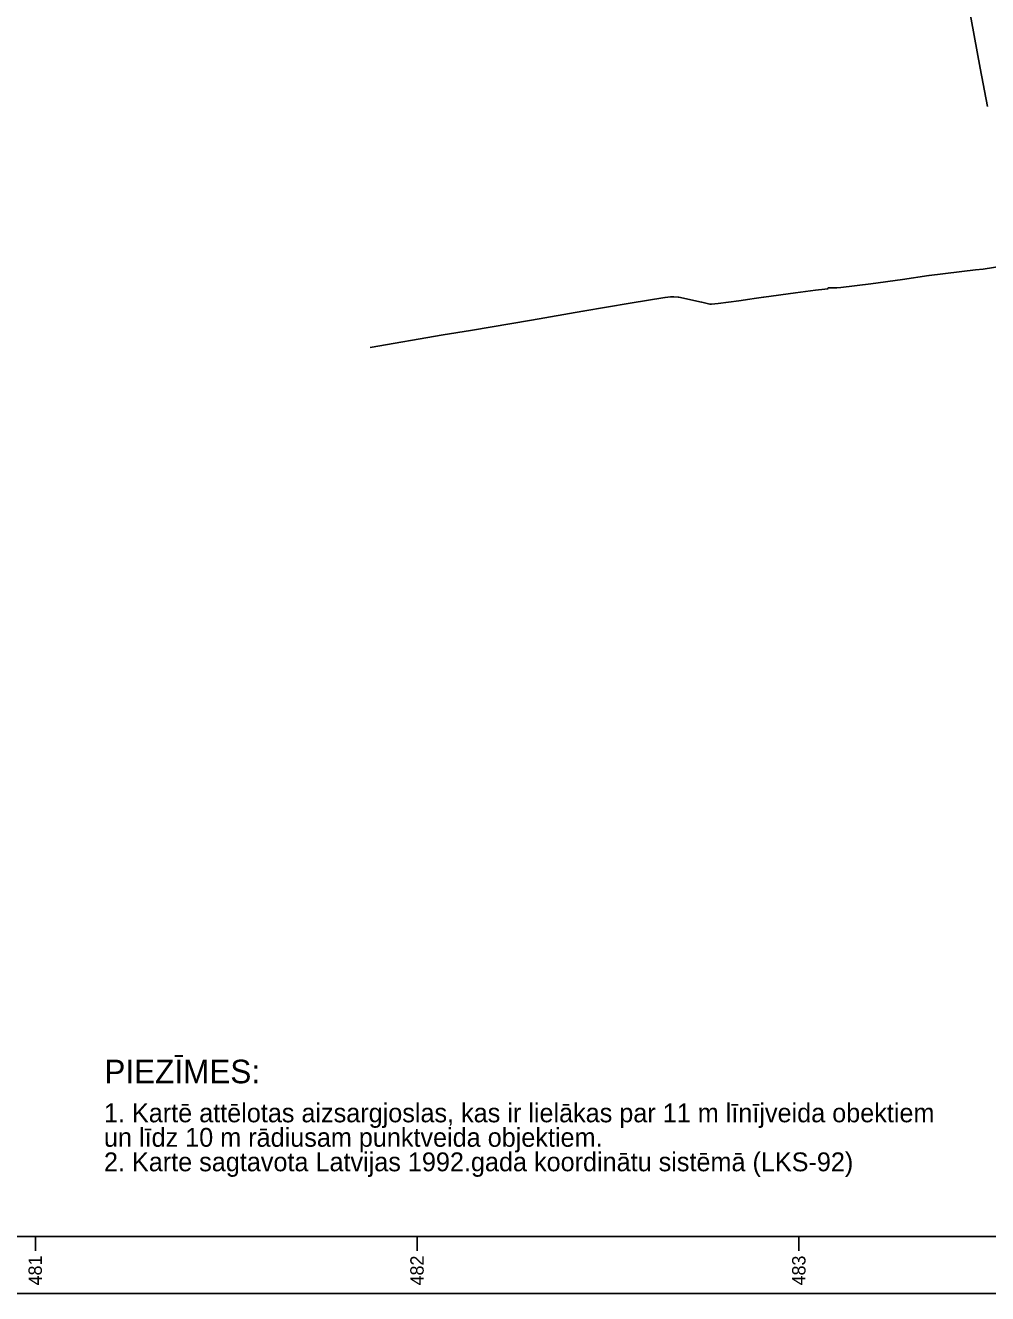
# Model space of a CAD drawing. Extents: x 468834 to 503362, y 294936 to 320859.
# Drawn here: x 480974 to 483494, y 294936 to 298258 of the extents above; entities that cross this region are included whole.
import ezdxf

# ---------------------------------------------------------------- set-up
doc = ezdxf.new("R2010")
doc.units = 0
for name, color, linetype in [('7311080102_vides un dabas resursu aizsardzības aizsargjoslas teritorija ap purvu ar platību lielāku par 100 hektāriem', 7, 'Continuous'), ('Koplietošanas novadgrāvis', 7, 'Continuous'), ('ramis', 7, 'Continuous'), ('Teksts', 7, 'Continuous')]:
    doc.layers.add(name, color=color, linetype=linetype)

msp = doc.modelspace()

# ---------------------------------------------------------------- linework, layer by layer
at = {"layer": '7311080102_vides un dabas resursu aizsardzības aizsargjoslas teritorija ap purvu ar platību lielāku par 100 hektāriem'}
for p, q in [((483442.9, 298316.8), (483474.8, 298146)), ((483474.8, 298146), (483494.1, 298045.6))]:
    msp.add_line(p, q, dxfattribs=at)
at = {"layer": 'Koplietošanas novadgrāvis'}
for points in [[(483340.7, 297602.9), (483462.5, 297617.3)], [(483462.5, 297617.3), (483482.5, 297619.7), (483558.5, 297631.4), (483558.6, 297631.4), (483558.7, 297631.4), (483573.6, 297633.5)], [(483075.7, 297570.4), (483079.4, 297570.6), (483079.6, 297570.6), (483079.7, 297570.6), (483087.4, 297570.8), (483087.7, 297570.8), (483087.9, 297570.8), (483098.9, 297570.6), (483109.9, 297571.4), (483188.6, 297580.9), (483271.3, 297592.4), (483340.2, 297602.8), (483340.4, 297602.8), (483340.5, 297602.9), (483340.7, 297602.9)], [(482882.9, 297542.6), (482907.4, 297546.2), (482907.5, 297546.2), (482907.5, 297546.2), (482990.9, 297557.5), (482990.9, 297557.5), (482990.9, 297557.5), (483043.1, 297564.4), (483043.2, 297564.4), (483043.3, 297564.4), (483067.3, 297566.9), (483067.6, 297566.9), (483067.8, 297566.9), (483076.2, 297567.4)], [(483076.2, 297567.4), (483075.7, 297570.4)], [(481876.9, 297413.9), (482067.7, 297447), (482067.8, 297447.1), (482067.8, 297447.1), (482139.4, 297458.4), (482299.8, 297485.8), (482434.2, 297508.9), (482557.7, 297530.2), (482557.7, 297530.2), (482557.8, 297530.2), (482649, 297545.3), (482649.3, 297545.3), (482649.6, 297545.4), (482663.7, 297546.7), (482664, 297546.7), (482664.3, 297546.8), (482671.3, 297547), (482671.7, 297547), (482672.1, 297547), (482683.7, 297546.3), (482684.4, 297546.2), (482685.2, 297546.1), (482745, 297532.7), (482745.1, 297532.7), (482745.2, 297532.7), (482766.9, 297527.4), (482770.9, 297527.3), (482787.9, 297529.4), (482842.1, 297536.7), (482871.5, 297541)], [(482871.5, 297541), (482882.9, 297542.6)]]:
    msp.add_lwpolyline(points, dxfattribs=at)
at = {"layer": 'ramis'}
for p, q in [((500923.3, 295086.2), (468983.8, 295086.2)), ((481000, 295086.2), (481000, 295048.1)), ((482000, 295086.2), (482000, 295048.1)), ((483000, 295086.2), (483000, 295048.1))]:
    msp.add_line(p, q, dxfattribs=at)
msp.add_lwpolyline([(501073.3, 316810.3), (468833.8, 316810.3), (468833.8, 294936.2), (501073.3, 294936.2)], close=True, dxfattribs=at)

# ---------------------------------------------------------------- texts
for s, p in [('481', (481017, 294957.8)), ('482', (482017, 294957.8)), ('483', (483017, 294957.8))]:
    msp.add_text(s, height=35, rotation=90, dxfattribs=at).set_placement(p)
at = {"layer": 'Teksts'}
for s, height, p in [('PIEZĪMES: ', 61.69, (481180.6, 295487.2)), ('1. Kartē attēlotas aizsargjoslas, kas ir lielākas par 11 m līnījveida obektiem', 49.351, (481179.6, 295385)), ('un līdz 10 m rādiusam punktveida objektiem.', 49.351, (481179.6, 295320.9)), ('2. Karte sagtavota Latvijas 1992.gada koordinātu sistēmā (LKS-92)  ', 49.351, (481179.6, 295256.7))]:
    msp.add_text(s, height=height, dxfattribs=at).set_placement(p)

doc.saveas('drawing.dxf')
